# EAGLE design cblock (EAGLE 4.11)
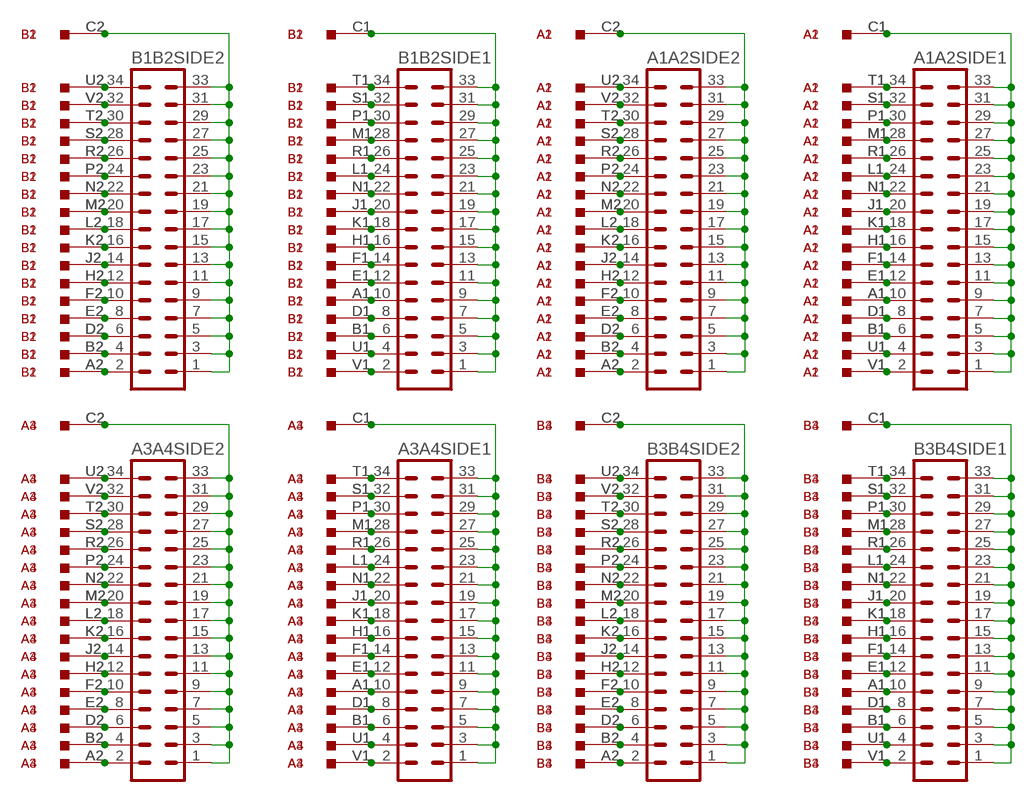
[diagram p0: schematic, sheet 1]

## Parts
A1  M916  [H807]
A1A2SIDE1  MA17-2  [MA17-2]
A1A2SIDE2  MA17-2  [MA17-2]
A2  M916  [H807]
A3  M916  [H807]
A3A4SIDE1  MA17-2  [MA17-2]
A3A4SIDE2  MA17-2  [MA17-2]
A4  M916  [H807]
B1  M916  [H807]
B1B2SIDE1  MA17-2  [MA17-2]
B1B2SIDE2  MA17-2  [MA17-2]
B2  M916  [H807]
B3  M916  [H807]
B3B4SIDE1  MA17-2  [MA17-2]
B3B4SIDE2  MA17-2  [MA17-2]
B4  M916  [H807]

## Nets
N$1: B1.C2 B1B2SIDE2.1 B1B2SIDE2.3 B1B2SIDE2.5 B1B2SIDE2.7 B1B2SIDE2.9 B1B2SIDE2.11 B1B2SIDE2.13 B1B2SIDE2.15 B1B2SIDE2.17 B1B2SIDE2.19 B1B2SIDE2.21 B1B2SIDE2.23 B1B2SIDE2.25 B1B2SIDE2.27 B1B2SIDE2.29 B1B2SIDE2.31 B1B2SIDE2.33 B2.C2
N$2: B1.A2 B1B2SIDE2.2 B2.A2
N$3: B1.B2 B1B2SIDE2.4 B2.B2
N$4: B1.D2 B1B2SIDE2.6 B2.D2
N$5: B1.E2 B1B2SIDE2.8 B2.E2
N$6: B1.F2 B1B2SIDE2.10 B2.F2
N$7: B1.H2 B1B2SIDE2.12 B2.H2
N$8: B1.J2 B1B2SIDE2.14 B2.J2
N$9: B1.K2 B1B2SIDE2.16 B2.K2
N$10: B1.L2 B1B2SIDE2.18 B2.L2
N$11: B1.M2 B1B2SIDE2.20 B2.M2
N$12: B1.N2 B1B2SIDE2.22 B2.N2
N$13: B1.P2 B1B2SIDE2.24 B2.P2
N$14: B1.R2 B1B2SIDE2.26 B2.R2
N$15: B1.S2 B1B2SIDE2.28 B2.S2
N$16: B1.T2 B1B2SIDE2.30 B2.T2
N$17: B1.U2 B1B2SIDE2.34 B2.U2
N$18: B1.V2 B1B2SIDE2.32 B2.V2
N$19: B1.A1 B1B2SIDE1.10 B2.A1
N$20: B1.B1 B1B2SIDE1.6 B2.B1
N$21: B1.D1 B1B2SIDE1.8 B2.D1
N$22: B1.E1 B1B2SIDE1.12 B2.E1
N$23: B1.F1 B1B2SIDE1.14 B2.F1
N$24: B1.H1 B1B2SIDE1.16 B2.H1
N$25: B1.J1 B1B2SIDE1.20 B2.J1
N$26: B1.K1 B1B2SIDE1.18 B2.K1
N$27: B1.L1 B1B2SIDE1.24 B2.L1
N$28: B1.M1 B1B2SIDE1.28 B2.M1
N$29: B1.N1 B1B2SIDE1.22 B2.N1
N$30: B1.P1 B1B2SIDE1.30 B2.P1
N$31: B1.R1 B1B2SIDE1.26 B2.R1
N$32: B1.S1 B1B2SIDE1.32 B2.S1
N$33: B1.T1 B1B2SIDE1.34 B2.T1
N$34: B1.U1 B1B2SIDE1.4 B2.U1
N$35: B1.V1 B1B2SIDE1.2 B2.V1
N$36: B1.C1 B1B2SIDE1.1 B1B2SIDE1.3 B1B2SIDE1.5 B1B2SIDE1.7 B1B2SIDE1.9 B1B2SIDE1.11 B1B2SIDE1.13 B1B2SIDE1.15 B1B2SIDE1.17 B1B2SIDE1.19 B1B2SIDE1.21 B1B2SIDE1.23 B1B2SIDE1.25 B1B2SIDE1.27 B1B2SIDE1.29 B1B2SIDE1.31 B1B2SIDE1.33 B2.C1
N$37: A1.C2 A1A2SIDE2.1 A1A2SIDE2.3 A1A2SIDE2.5 A1A2SIDE2.7 A1A2SIDE2.9 A1A2SIDE2.11 A1A2SIDE2.13 A1A2SIDE2.15 A1A2SIDE2.17 A1A2SIDE2.19 A1A2SIDE2.21 A1A2SIDE2.23 A1A2SIDE2.25 A1A2SIDE2.27 A1A2SIDE2.29 A1A2SIDE2.31 A1A2SIDE2.33 A2.C2
N$38: A1.A2 A1A2SIDE2.2 A2.A2
N$39: A1.B2 A1A2SIDE2.4 A2.B2
N$40: A1.D2 A1A2SIDE2.6 A2.D2
N$41: A1.E2 A1A2SIDE2.8 A2.E2
N$42: A1.F2 A1A2SIDE2.10 A2.F2
N$43: A1.H2 A1A2SIDE2.12 A2.H2
N$44: A1.J2 A1A2SIDE2.14 A2.J2
N$45: A1.K2 A1A2SIDE2.16 A2.K2
N$46: A1.L2 A1A2SIDE2.18 A2.L2
N$47: A1.M2 A1A2SIDE2.20 A2.M2
N$48: A1.N2 A1A2SIDE2.22 A2.N2
N$49: A1.P2 A1A2SIDE2.24 A2.P2
N$50: A1.R2 A1A2SIDE2.26 A2.R2
N$51: A1.S2 A1A2SIDE2.28 A2.S2
N$52: A1.T2 A1A2SIDE2.30 A2.T2
N$53: A1.U2 A1A2SIDE2.34 A2.U2
N$54: A1.V2 A1A2SIDE2.32 A2.V2
N$55: A1.A1 A1A2SIDE1.10 A2.A1
N$56: A1.B1 A1A2SIDE1.6 A2.B1
N$57: A1.D1 A1A2SIDE1.8 A2.D1
N$58: A1.E1 A1A2SIDE1.12 A2.E1
N$59: A1.F1 A1A2SIDE1.14 A2.F1
N$60: A1.H1 A1A2SIDE1.16 A2.H1
N$61: A1.J1 A1A2SIDE1.20 A2.J1
N$62: A1.K1 A1A2SIDE1.18 A2.K1
N$63: A1.L1 A1A2SIDE1.24 A2.L1
N$64: A1.M1 A1A2SIDE1.28 A2.M1
N$65: A1.N1 A1A2SIDE1.22 A2.N1
N$66: A1.P1 A1A2SIDE1.30 A2.P1
N$67: A1.R1 A1A2SIDE1.26 A2.R1
N$68: A1.S1 A1A2SIDE1.32 A2.S1
N$69: A1.T1 A1A2SIDE1.34 A2.T1
N$70: A1.U1 A1A2SIDE1.4 A2.U1
N$71: A1.V1 A1A2SIDE1.2 A2.V1
N$72: A1.C1 A1A2SIDE1.1 A1A2SIDE1.3 A1A2SIDE1.5 A1A2SIDE1.7 A1A2SIDE1.9 A1A2SIDE1.11 A1A2SIDE1.13 A1A2SIDE1.15 A1A2SIDE1.17 A1A2SIDE1.19 A1A2SIDE1.21 A1A2SIDE1.23 A1A2SIDE1.25 A1A2SIDE1.27 A1A2SIDE1.29 A1A2SIDE1.31 A1A2SIDE1.33 A2.C1
N$145: A3.C2 A3A4SIDE2.1 A3A4SIDE2.3 A3A4SIDE2.5 A3A4SIDE2.7 A3A4SIDE2.9 A3A4SIDE2.11 A3A4SIDE2.13 A3A4SIDE2.15 A3A4SIDE2.17 A3A4SIDE2.19 A3A4SIDE2.21 A3A4SIDE2.23 A3A4SIDE2.25 A3A4SIDE2.27 A3A4SIDE2.29 A3A4SIDE2.31 A3A4SIDE2.33 A4.C2
N$146: A3.A2 A3A4SIDE2.2 A4.A2
N$147: A3.B2 A3A4SIDE2.4 A4.B2
N$148: A3.D2 A3A4SIDE2.6 A4.D2
N$149: A3.E2 A3A4SIDE2.8 A4.E2
N$150: A3.F2 A3A4SIDE2.10 A4.F2
N$151: A3.H2 A3A4SIDE2.12 A4.H2
N$152: A3.J2 A3A4SIDE2.14 A4.J2
N$153: A3.K2 A3A4SIDE2.16 A4.K2
N$154: A3.L2 A3A4SIDE2.18 A4.L2
N$155: A3.M2 A3A4SIDE2.20 A4.M2
N$156: A3.N2 A3A4SIDE2.22 A4.N2
N$157: A3.P2 A3A4SIDE2.24 A4.P2
N$158: A3.R2 A3A4SIDE2.26 A4.R2
N$159: A3.S2 A3A4SIDE2.28 A4.S2
N$160: A3.T2 A3A4SIDE2.30 A4.T2
N$161: A3.U2 A3A4SIDE2.34 A4.U2
N$162: A3.V2 A3A4SIDE2.32 A4.V2
N$163: A3.A1 A3A4SIDE1.10 A4.A1
N$164: A3.B1 A3A4SIDE1.6 A4.B1
N$165: A3.D1 A3A4SIDE1.8 A4.D1
N$166: A3.E1 A3A4SIDE1.12 A4.E1
N$167: A3.F1 A3A4SIDE1.14 A4.F1
N$168: A3.H1 A3A4SIDE1.16 A4.H1
N$169: A3.J1 A3A4SIDE1.20 A4.J1
N$170: A3.K1 A3A4SIDE1.18 A4.K1
N$171: A3.L1 A3A4SIDE1.24 A4.L1
N$172: A3.M1 A3A4SIDE1.28 A4.M1
N$173: A3.N1 A3A4SIDE1.22 A4.N1
N$174: A3.P1 A3A4SIDE1.30 A4.P1
N$175: A3.R1 A3A4SIDE1.26 A4.R1
N$176: A3.S1 A3A4SIDE1.32 A4.S1
N$177: A3.T1 A3A4SIDE1.34 A4.T1
N$178: A3.U1 A3A4SIDE1.4 A4.U1
N$179: A3.V1 A3A4SIDE1.2 A4.V1
N$180: A3.C1 A3A4SIDE1.1 A3A4SIDE1.3 A3A4SIDE1.5 A3A4SIDE1.7 A3A4SIDE1.9 A3A4SIDE1.11 A3A4SIDE1.13 A3A4SIDE1.15 A3A4SIDE1.17 A3A4SIDE1.19 A3A4SIDE1.21 A3A4SIDE1.23 A3A4SIDE1.25 A3A4SIDE1.27 A3A4SIDE1.29 A3A4SIDE1.31 A3A4SIDE1.33 A4.C1
N$253: B3.C2 B3B4SIDE2.1 B3B4SIDE2.3 B3B4SIDE2.5 B3B4SIDE2.7 B3B4SIDE2.9 B3B4SIDE2.11 B3B4SIDE2.13 B3B4SIDE2.15 B3B4SIDE2.17 B3B4SIDE2.19 B3B4SIDE2.21 B3B4SIDE2.23 B3B4SIDE2.25 B3B4SIDE2.27 B3B4SIDE2.29 B3B4SIDE2.31 B3B4SIDE2.33 B4.C2
N$254: B3.A2 B3B4SIDE2.2 B4.A2
N$255: B3.B2 B3B4SIDE2.4 B4.B2
N$256: B3.D2 B3B4SIDE2.6 B4.D2
N$257: B3.E2 B3B4SIDE2.8 B4.E2
N$258: B3.F2 B3B4SIDE2.10 B4.F2
N$259: B3.H2 B3B4SIDE2.12 B4.H2
N$260: B3.J2 B3B4SIDE2.14 B4.J2
N$261: B3.K2 B3B4SIDE2.16 B4.K2
N$262: B3.L2 B3B4SIDE2.18 B4.L2
N$263: B3.M2 B3B4SIDE2.20 B4.M2
N$264: B3.N2 B3B4SIDE2.22 B4.N2
N$265: B3.P2 B3B4SIDE2.24 B4.P2
N$266: B3.R2 B3B4SIDE2.26 B4.R2
N$267: B3.S2 B3B4SIDE2.28 B4.S2
N$268: B3.T2 B3B4SIDE2.30 B4.T2
N$269: B3.U2 B3B4SIDE2.34 B4.U2
N$270: B3.V2 B3B4SIDE2.32 B4.V2
N$271: B3.A1 B3B4SIDE1.10 B4.A1
N$272: B3.B1 B3B4SIDE1.6 B4.B1
N$273: B3.D1 B3B4SIDE1.8 B4.D1
N$274: B3.E1 B3B4SIDE1.12 B4.E1
N$275: B3.F1 B3B4SIDE1.14 B4.F1
N$276: B3.H1 B3B4SIDE1.16 B4.H1
N$277: B3.J1 B3B4SIDE1.20 B4.J1
N$278: B3.K1 B3B4SIDE1.18 B4.K1
N$279: B3.L1 B3B4SIDE1.24 B4.L1
N$280: B3.M1 B3B4SIDE1.28 B4.M1
N$281: B3.N1 B3B4SIDE1.22 B4.N1
N$282: B3.P1 B3B4SIDE1.30 B4.P1
N$283: B3.R1 B3B4SIDE1.26 B4.R1
N$284: B3.S1 B3B4SIDE1.32 B4.S1
N$285: B3.T1 B3B4SIDE1.34 B4.T1
N$286: B3.U1 B3B4SIDE1.4 B4.U1
N$287: B3.V1 B3B4SIDE1.2 B4.V1
N$288: B3.C1 B3B4SIDE1.1 B3B4SIDE1.3 B3B4SIDE1.5 B3B4SIDE1.7 B3B4SIDE1.9 B3B4SIDE1.11 B3B4SIDE1.13 B3B4SIDE1.15 B3B4SIDE1.17 B3B4SIDE1.19 B3B4SIDE1.21 B3B4SIDE1.23 B3B4SIDE1.25 B3B4SIDE1.27 B3B4SIDE1.29 B3B4SIDE1.31 B3B4SIDE1.33 B4.C1

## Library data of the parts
A1-A4 B1-B4 = dec-m:M916: Simple 36 pin connector/wire cable
A1A2SIDE1 A1A2SIDE2 A3A4SIDE1 A3A4SIDE2 B1B2SIDE1 B1B2SIDE2 B3B4SIDE1 B3B4SIDE2 = con-lstb:MA17-2: PIN HEADER

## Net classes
1 Power: width 0.305 mm, drill 0.305 mm

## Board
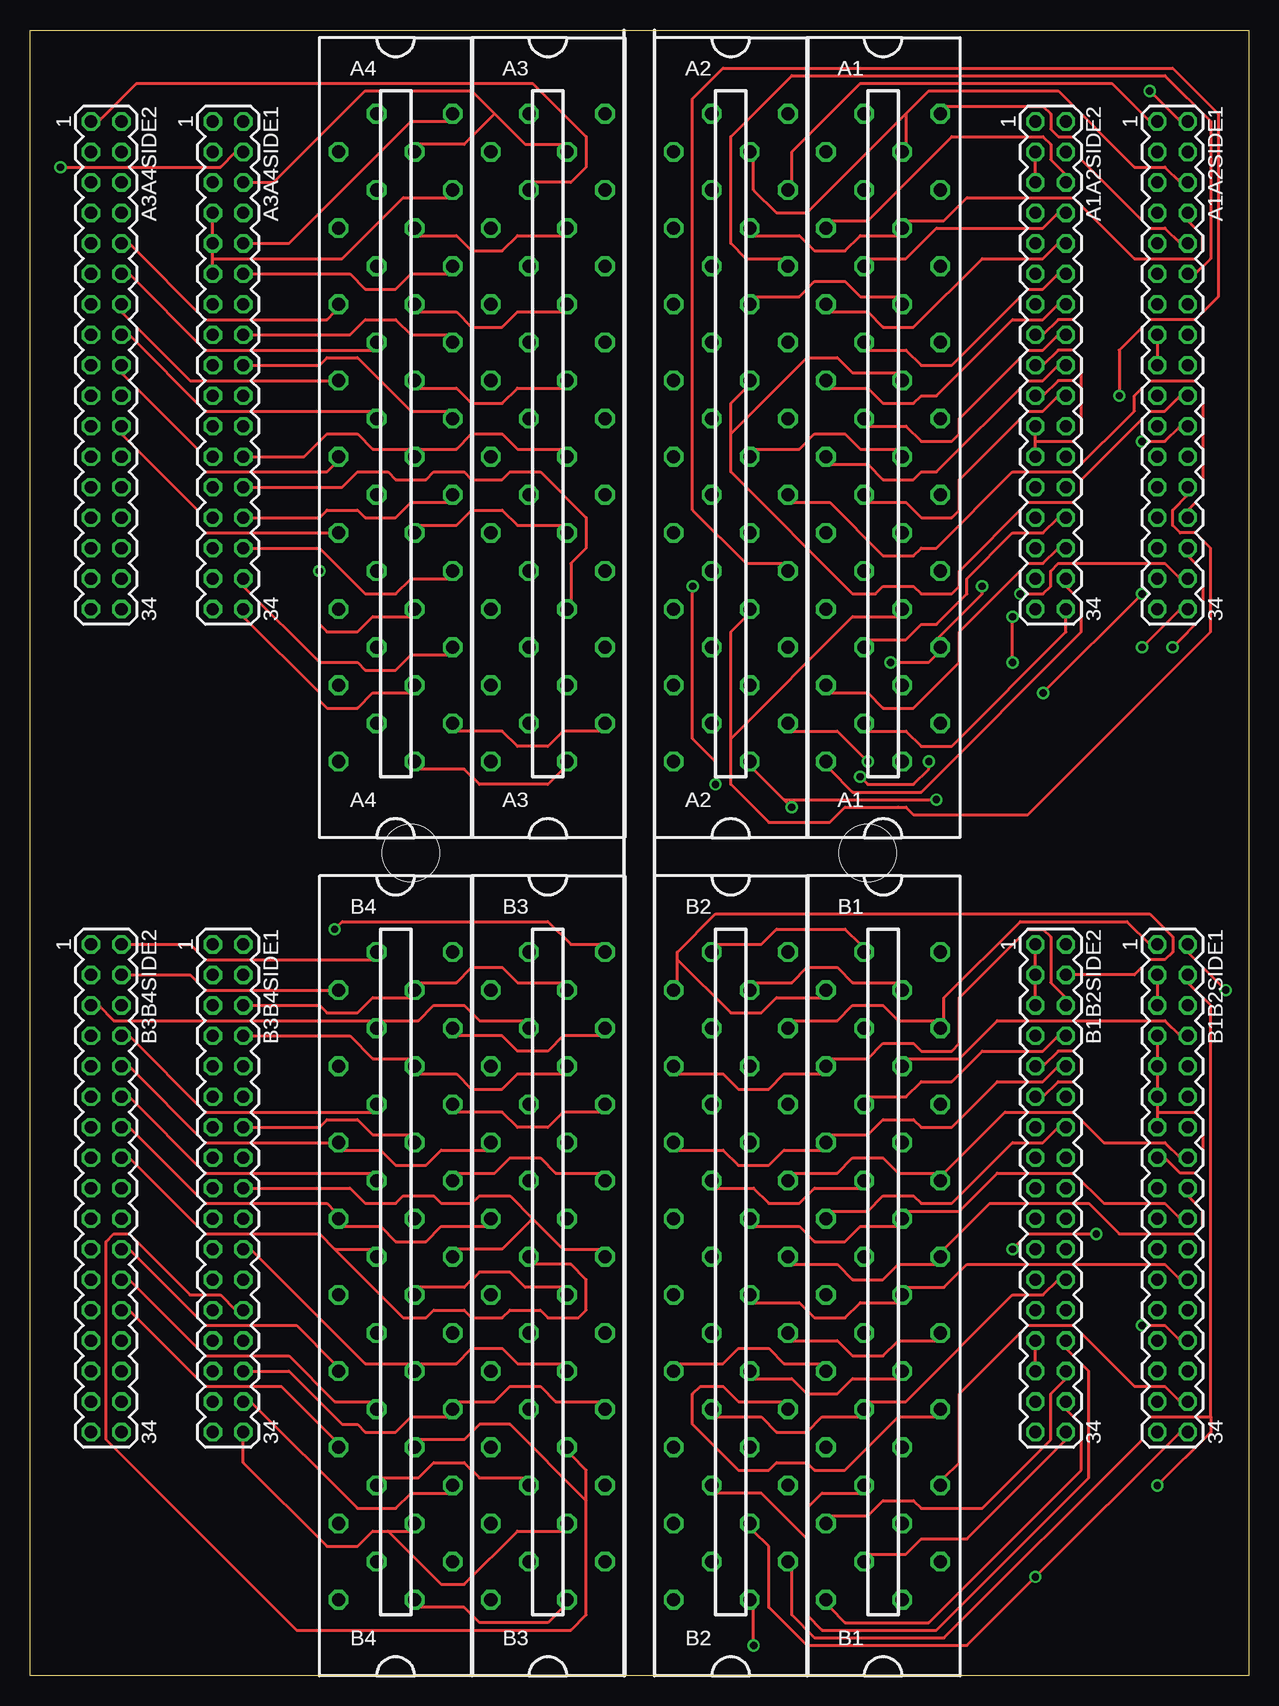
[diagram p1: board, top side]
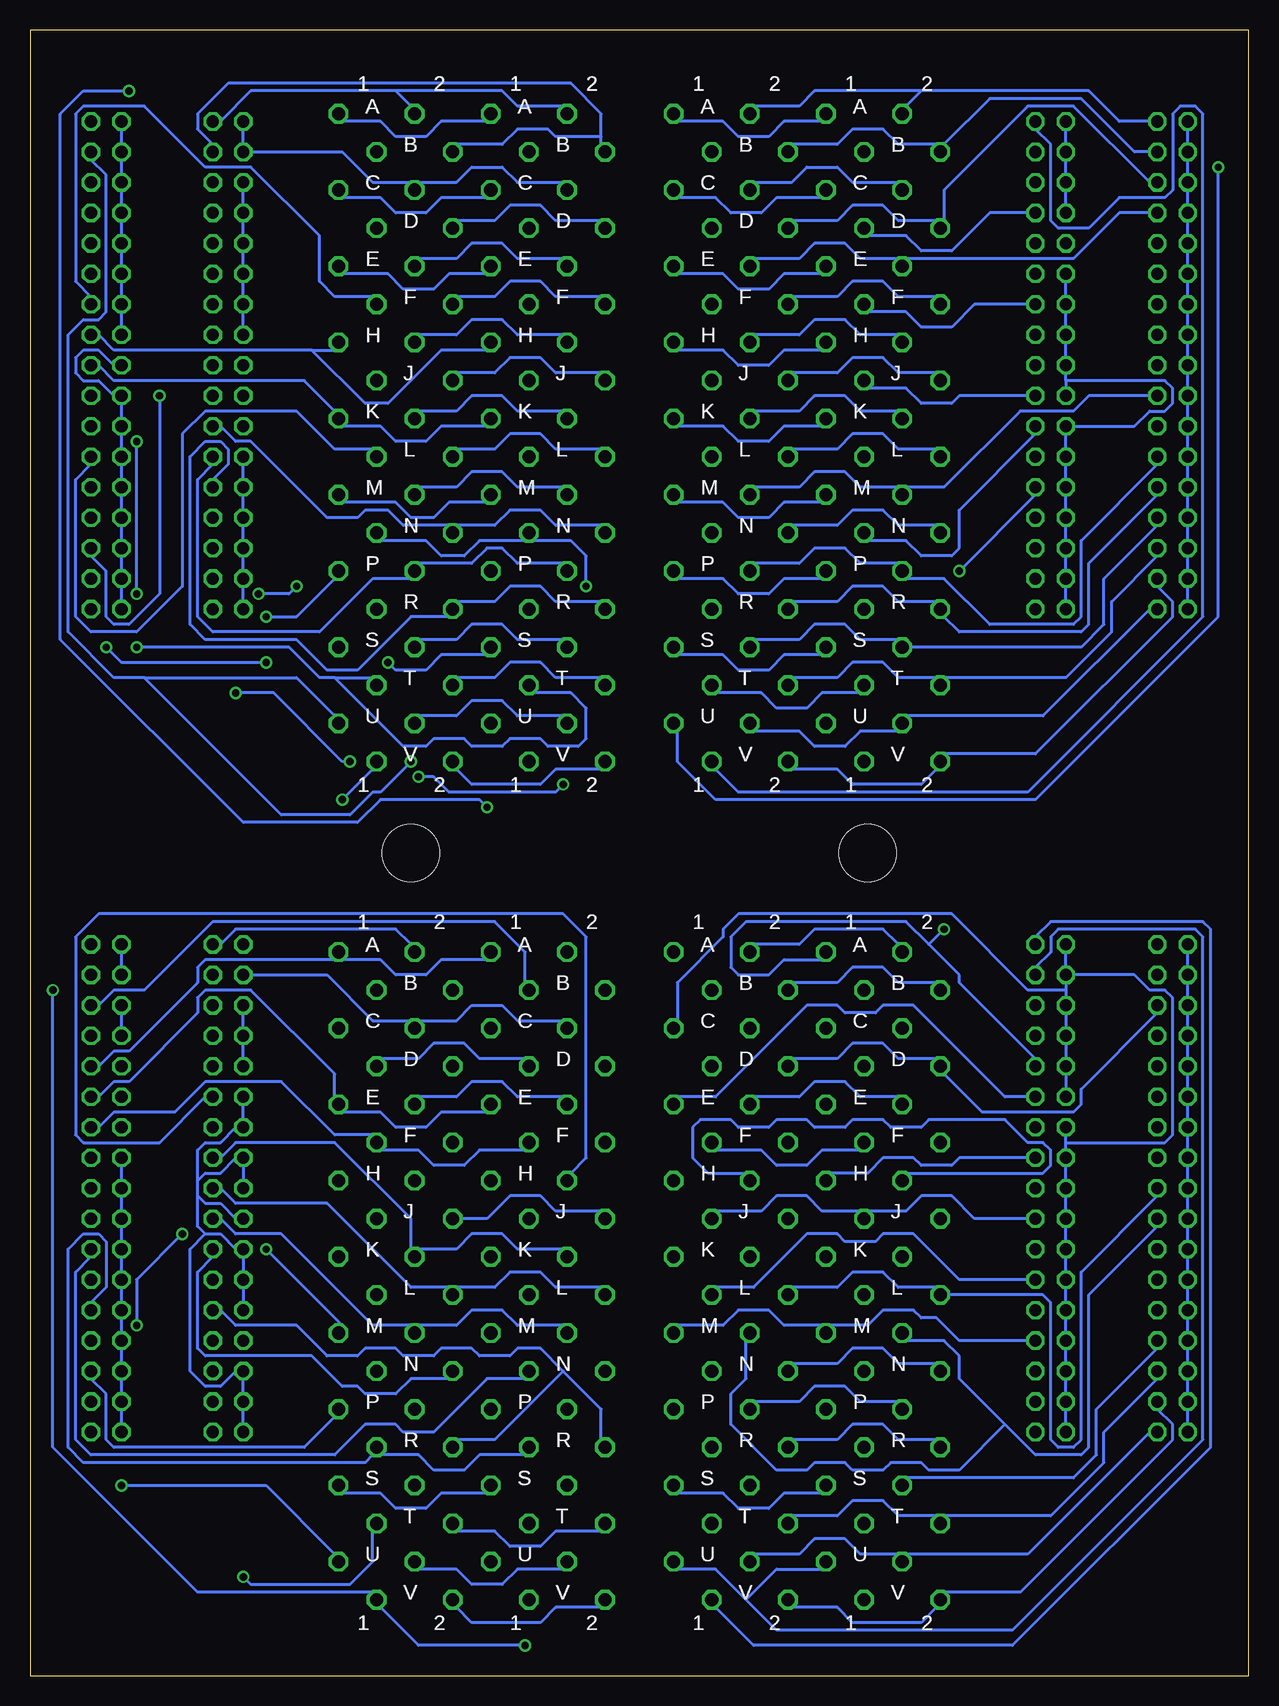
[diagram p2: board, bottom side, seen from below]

Size 101.6 x 137.16 mm. Coordinates in mm from the lower left corner, seen from the top.
Outline: 101.6,0 52.07,0 49.53,0 0,0 0,137.16 49.53,137.16 52.07,137.16 101.6,137.16 101.6,0
Copper layers (1*16): Top 0.035mm / dielectric 1.5mm / Bottom 0.035mm
Design rules "custompcb": minimum track width 10mil, minimum drill 24mil, track to track 12mil, track to pad 12mil, pad to pad 12mil, via to via 12mil, smd to smd 12mil, copper to edge 40mil, drill to drill 12mil, minimum pad ring 10mil, minimum via ring 8mil, stop-mask expansion 0mil, vias tented up to drill 0mil, thermal gap 10mil
Holes 4.78 mm at 31.75,68.58 69.85,68.58

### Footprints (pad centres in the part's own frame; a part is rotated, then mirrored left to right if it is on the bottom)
H807 = drill 1.092 octagon: A1 4.763,28.575; A2 -1.587,28.575; B1 1.587,25.4; B2 -4.763,25.4; C1 4.763,22.225; C2 -1.587,22.225; D1 1.587,19.05; D2 -4.763,19.05; E1 4.763,15.875; E2 -1.587,15.875; F1 1.587,12.7; F2 -4.763,12.7; H1 4.763,9.525; H2 -1.587,9.525; J1 1.587,6.35; J2 -4.763,6.35; K1 4.763,3.175; K2 -1.587,3.175; L1 1.587,0; L2 -4.763,0; M1 4.763,-3.175; M2 -1.587,-3.175; N1 1.587,-6.35; N2 -4.763,-6.35; P1 4.763,-9.525; P2 -1.587,-9.525; R1 1.587,-12.7; R2 -4.763,-12.7; S1 4.763,-15.875; S2 -1.587,-15.875; T1 1.587,-19.05; T2 -4.763,-19.05; U1 4.763,-22.225; U2 -1.587,-22.225; V1 1.587,-25.4; V2 -4.763,-25.4
MA17-2 = drill 1.016 octagon: 1 -20.32,-1.27; 2 -20.32,1.27; 3 -17.78,-1.27; 4 -17.78,1.27; 5 -15.24,-1.27; 6 -15.24,1.27; 7 -12.7,-1.27; 8 -12.7,1.27; 9 -10.16,-1.27; 10 -10.16,1.27; 11 -7.62,-1.27; 12 -7.62,1.27; 13 -5.08,-1.27; 14 -5.08,1.27; 15 -2.54,-1.27; 16 -2.54,1.27; 17 0,-1.27; 18 0,1.27; 19 2.54,-1.27; 20 2.54,1.27; 21 5.08,-1.27; 22 5.08,1.27; 23 7.62,-1.27; 24 7.62,1.27; 25 10.16,-1.27; 26 10.16,1.27; 27 12.7,-1.27; 28 12.7,1.27; 29 15.24,-1.27; 30 15.24,1.27; 31 17.78,-1.27; 32 17.78,1.27; 33 20.32,-1.27; 34 20.32,1.27

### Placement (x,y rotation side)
A1  71.12,101.6 0 top
A1A2SIDE1  95.25,109.22 270 top
A1A2SIDE2  85.09,109.22 270 top
A2  58.42,101.6 0 top
A3  43.18,101.6 0 top
A3A4SIDE1  16.51,109.22 270 top
A3A4SIDE2  6.35,109.22 270 top
A4  30.48,101.6 0 top
B1  71.12,31.75 0 top
B1B2SIDE1  95.25,40.64 270 top
B1B2SIDE2  85.09,40.64 270 top
B2  58.42,31.75 0 top
B3  43.18,31.75 0 top
B3B4SIDE1  16.51,40.64 270 top
B3B4SIDE2  6.35,40.64 270 top
B4  30.48,31.75 0 top

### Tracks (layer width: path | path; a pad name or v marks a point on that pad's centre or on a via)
N$1
  Top 0.254: B1B2SIDE2.27 83.82,27.3 83.82,26.04 B1B2SIDE2.29 | B1B2SIDE2.1 83.82,60.33 83.82,59.05 B1B2SIDE2.3 83.82,57.78 83.82,56.52 B1B2SIDE2.5 | B1B2SIDE2.11 84.45,48.26 85.72,49.53 87,49.53 87.63,50.16 87.63,51.44 87,52.07 85.72,52.07 84.45,50.8 B1B2SIDE2.9
  Bottom 0.254: B1B2SIDE2.33 83.82,20.95 83.82,22.23 B1B2SIDE2.31 83.82,23.5 83.82,24.77 B1B2SIDE2.29 84.45,25.4 85.72,24.13 87,24.13 88.27,25.4 88.27,35.56 87,36.83 | B1B2SIDE2.25 83.82,31.11 83.82,32.38 B1B2SIDE2.23 83.82,33.66 83.82,34.92 B1B2SIDE2.21 84.45,35.56 85.72,36.83 87,36.83 | B1B2SIDE2.11 83.82,47.62 83.82,46.35 B1B2SIDE2.13 84.45,45.72 85.72,44.45 87,44.45 87.63,43.81 87.63,41.27 | 87.63,40.01 87,39.37 85.72,39.37 84.45,38.1 B1B2SIDE2.19 | 87.63,40.01 87.63,41.27 | 87.63,41.27 87,41.91 85.72,41.91 84.45,43.18 B1B2SIDE2.15 83.82,42.55 83.82,41.27 B1B2SIDE2.17 | 87,36.83 87.63,37.47 87.63,40.01 | B1B2SIDE2.9 83.82,51.44 83.82,52.7 B1B2SIDE2.7 83.82,53.98 83.82,55.24 B1B2SIDE2.5 | B1B2SIDE2.3 83.19,58.42 76.83,58.42 73.03,54.61 69.85,54.61 B1.C2 69.22,54.61 66.04,54.61 64.77,55.88 62.23,55.88 60.96,54.61 57.15,54.61 B2.C2
N$2
  Top 0.254: B2.A2 57.15,60.96 60.96,60.96 62.23,62.23 67.94,62.23 69.22,60.96 B1.A2
  Bottom 0.254: B1B2SIDE2.2 85.72,60.96 84.45,62.23 71.12,62.23 69.85,60.96 B1.A2
N$3
  Top 0.254: 53.98,59.69 53.98,57.78 B2.B2 | 53.98,59.69 53.98,60.33 57.15,63.5 93.34,63.5 95.25,61.59 95.25,60.33 94.61,59.69 93.34,59.69 92.08,58.42 87,58.42 B1B2SIDE2.4 | 53.98,59.69 58.42,55.24 60.96,55.24 62.23,56.52 66.04,56.52 B1.B2
N$4
  Top 0.254: B1B2SIDE2.6 86.36,56.52 85.09,57.78 85.09,61.59 84.45,62.23 83.19,62.23 77.47,56.52 77.47,52.7 76.83,52.07 74.3,52.07 73.66,52.7 71.12,52.7 69.85,51.44 66.67,51.44 B1.D2 66.04,50.16 62.87,50.16 61.59,48.9 59.05,48.9 57.78,50.16 53.98,50.16 B2.D2
N$5
  Top 0.254: B1B2SIDE2.8 85.72,53.34 84.45,52.07 79.38,52.07 76.83,49.53 74.3,49.53 73.03,48.26 69.85,48.26 B1.E2
  Bottom 0.254: B2.E2 57.15,48.26 60.96,48.26 62.23,49.53 64.77,49.53 66.04,48.26 69.22,48.26 B1.E2
N$6
  Top 0.254: B1B2SIDE2.10 85.72,50.8 84.45,49.53 80.64,49.53 76.83,45.72 74.3,45.72 73.66,46.35 71.12,46.35 69.85,45.09 66.67,45.09 B1.F2 66.04,43.81 62.87,43.81 61.59,42.55 59.05,42.55 57.78,43.81 53.98,43.81 B2.F2
N$7
  Top 0.254: B1.H2 69.22,40.64 65.41,40.64 64.14,39.37 61.59,39.37 60.33,40.64 57.15,40.64 B2.H2
  Bottom 0.254: B1B2SIDE2.12 87,48.26 90.81,44.45 97.16,44.45 97.79,45.09 97.79,61.59 95.89,63.5 57.15,63.5 55.24,61.59 55.24,43.18 56.52,41.91 B2.H2
N$8
  Top 0.254: B1B2SIDE2.14 85.72,45.72 84.45,44.45 81.92,44.45 76.83,39.37 74.3,39.37 73.66,40.01 71.12,40.01 69.85,38.73 66.67,38.73 B1.J2
  Bottom 0.254: B2.J2 53.98,38.73 57.78,38.73 59.05,40.01 61.59,40.01 63.5,38.1 66.04,38.1 B1.J2
N$9
  Bottom 0.254: B1B2SIDE2.16 85.72,43.18 84.45,44.45 76.2,44.45 69.85,38.1 69.85,35.56 B1.K2 69.22,35.56 66.04,35.56 64.77,36.83 62.23,36.83 60.96,35.56 57.15,35.56 B2.K2
N$10
  Bottom 0.254: B1B2SIDE2.18 85.72,40.64 84.45,39.37 76.83,39.37 69.85,32.38 66.67,32.38 B1.L2 66.04,32.38 62.87,32.38 61.59,33.66 59.05,33.66 57.78,32.38 53.98,32.38 B2.L2
N$11
  Bottom 0.254: B1B2SIDE2.20 85.72,38.1 84.45,36.83 80.64,36.83 73.03,29.21 69.85,29.21 B1.M2 69.22,29.21 66.04,29.21 64.77,30.48 62.23,30.48 60.96,29.21 57.15,29.21 B2.M2
N$12
  Top 0.254: B2.N2 53.98,26.04 57.78,26.04 59.05,27.3 61.59,27.3 62.87,26.04 66.04,26.04 B1.N2
  Bottom 0.254: B1B2SIDE2.22 86.36,34.92 87.63,33.66 87.63,27.3 87,26.67 78.11,26.67 75.56,24.13 74.3,24.13 73.66,23.5 71.12,23.5 69.85,24.77 66.67,24.77 B1.N2
N$13
  Top 0.254: B1B2SIDE2.24 85.72,33.02 84.45,31.75 81.92,31.75 73.03,22.86 69.85,22.86 B1.P2 69.22,21.59 66.04,21.59 64.77,20.32 62.23,20.32 60.96,21.59 57.15,21.59 B2.P2
N$14
  Bottom 0.254: 57.15,25.4 53.98,22.23 53.98,19.68 B2.R2 | 57.15,25.4 59.05,27.3 60.96,27.3 61.59,26.67 64.14,26.67 64.77,27.3 67.31,27.3 67.94,26.67 70.48,26.67 71.12,27.3 73.66,27.3 74.3,26.67 76.83,26.67 79.38,29.21 84.45,29.21 85.72,30.48 B1B2SIDE2.26 | 57.15,25.4 62.87,19.68 66.04,19.68 B1.R2
N$15
  Top 0.254: 64.77,11.43 64.77,13.97 66.04,15.24 69.22,15.24 B1.S2 | 64.77,11.43 64.77,5.08 66.04,3.81 75.56,3.81 88.27,16.51 88.27,25.4 86.36,27.3 B1B2SIDE2.28 | 64.77,11.43 60.96,15.24 57.15,15.24 B2.S2
N$16
  Top 0.254: B1B2SIDE2.30 86.36,24.77 85.09,23.5 85.09,19.68 79.38,13.97 74.3,13.97 73.66,14.61 71.12,14.61 69.85,13.34 66.67,13.34 B1.T2
  Bottom 0.254: B2.T2 53.98,12.06 57.78,12.06 59.05,10.79 61.59,10.79 62.87,12.06 66.04,12.06 B1.T2
N$17
  Top 0.254: B1B2SIDE2.34 86.36,19.68 78.11,11.43 74.3,11.43 73.03,10.16 69.85,10.16 B1.U2
  Bottom 0.254: B2.U2 57.15,8.89 60.96,8.89 62.23,7.62 64.77,7.62 66.04,8.89 69.22,8.89 B1.U2
N$18
  Top 0.254: B1B2SIDE2.32 86.36,22.23 87.63,20.95 87.63,17.14 74.93,4.45 67.94,4.45 66.67,5.71 B1.V2
  Bottom 0.254: B2.V2 53.98,5.71 57.78,5.71 59.05,4.45 64.77,4.45 66.04,5.71 B1.V2
N$19
  Bottom 0.254: B1B2SIDE1.10 95.89,50.8 94.61,52.07 93.34,52.07 87.63,57.78 87.63,59.05 87,59.69 76.2,59.69 B1.A1 75.56,59.69 72.39,59.69 71.12,58.42 68.58,58.42 67.31,59.69 63.5,59.69 B2.A1
N$20
  Top 0.254: B1.B1 72.39,57.78 68.58,57.78 67.31,59.05 64.77,59.05 63.5,57.78 60.33,57.78 B2.B1
  Bottom 0.254: B1B2SIDE1.6 95.89,55.88 94.61,57.15 92.08,57.15 86.36,62.87 62.87,62.87 60.33,60.33 60.33,57.78 B2.B1
N$21
  Top 0.254: B1B2SIDE1.8 95.89,53.34 94.61,54.61 80.64,54.61 77.47,51.44 73.03,51.44 B1.D1
  Bottom 0.254: B2.D1 60.33,51.44 64.14,51.44 65.41,52.7 67.94,52.7 69.22,51.44 72.39,51.44 B1.D1
N$22
  Bottom 0.254: B1B2SIDE1.12 95.89,48.26 94.61,49.53 93.34,49.53 87.63,55.24 87.63,56.52 87,57.15 83.19,57.15 76.2,50.16 76.2,48.26 B1.E1 75.56,46.99 72.39,46.99 71.12,45.72 68.58,45.72 67.31,46.99 63.5,46.99 B2.E1
N$23
  Bottom 0.254: B1B2SIDE1.14 95.89,45.72 94.61,46.99 89.53,46.99 87,49.53 80.64,49.53 76.2,45.09 73.03,45.09 B1.F1 72.39,43.81 69.22,43.81 67.94,42.55 65.41,42.55 64.14,43.81 60.33,43.81 B2.F1
N$24
  Top 0.254: B1B2SIDE1.16 95.89,43.18 94.61,44.45 89.53,44.45 87,46.99 81.28,46.99 76.2,41.91 B1.H1 75.56,41.91 72.39,41.91 71.12,43.18 68.58,43.18 67.31,41.91 63.5,41.91 B2.H1
N$25
  Top 0.254: B1B2SIDE1.20 95.89,38.1 94.61,39.37 89.53,39.37 87,41.91 80.64,41.91 77.47,38.73 73.03,38.73 B1.J1 72.39,37.47 69.22,37.47 67.94,36.2 65.41,36.2 64.14,37.47 60.33,37.47 B2.J1
N$26
  Top 0.254: B1B2SIDE1.18 96.52,40.01 97.79,38.73 97.79,37.47 97.16,36.83 90.81,36.83 88.27,39.37 80.01,39.37 76.2,35.56 B1.K1 75.56,34.29 72.39,34.29 71.12,33.02 68.58,33.02 67.31,34.29 63.5,34.29 B2.K1
N$27
  Top 0.254: B1B2SIDE1.24 95.89,33.02 94.61,34.29 78.11,34.29 76.2,32.38 73.03,32.38 B1.L1 72.39,31.11 69.22,31.11 67.94,29.84 65.41,29.84 64.14,31.11 60.33,31.11 B2.L1
N$28  (via drill 0.61)
  Top 0.254: v92.71,29.21 94.61,29.21 95.89,27.94 B1B2SIDE1.28 | v88.9,36.83 83.19,36.83 v81.92,35.56 | B2.M1 63.5,27.94 67.31,27.94 68.58,26.67 71.12,26.67 72.39,27.94 75.56,27.94 B1.M1
  Bottom 0.254: v92.71,29.21 92.71,33.02 v88.9,36.83 | v81.92,35.56 75.56,29.21 B1.M1
N$29
  Top 0.254: B1.N1 72.39,24.77 68.58,24.77 67.31,23.5 64.77,23.5 63.5,24.77 60.33,24.77 B2.N1
  Bottom 0.254: B1B2SIDE1.22 96.52,34.92 97.79,33.66 97.79,19.68 96.52,18.41 76.2,18.41 73.66,20.95 71.12,20.95 70.48,20.32 67.94,20.32 63.5,24.77 60.33,24.77 B2.N1
N$30
  Top 0.254: B2.P1 62.87,22.86 59.05,22.86 57.78,24.13 55.88,24.13 55.24,23.5 55.24,20.95 59.05,17.14 61.59,17.14 62.23,17.78 64.77,17.78 65.41,17.14 67.94,17.14 72.39,21.59 75.56,21.59 B1.P1
  Bottom 0.254: B1B2SIDE1.30 96.52,24.77 95.25,23.5 95.25,19.68 94.61,19.05 78.74,19.05 76.2,21.59 B1.P1
N$31
  Bottom 0.254: B1B2SIDE1.26 96.52,31.11 95.25,32.38 95.25,36.2 95.89,36.83 97.16,36.83 98.42,35.56 98.42,19.05 97.16,17.78 73.66,17.78 73.03,18.41 B1.R1 72.39,18.41 69.22,18.41 67.94,17.14 65.41,17.14 64.14,18.41 60.33,18.41 B2.R1
N$32
  Top 0.254: B1B2SIDE1.32 95.89,22.86 94.61,24.13 92.08,24.13 87,29.21 83.19,29.21 77.47,23.5 77.47,17.78 76.2,16.51 B1.S1
  Bottom 0.254: B2.S1 63.5,15.24 67.31,15.24 68.58,13.97 71.12,13.97 72.39,15.24 75.56,15.24 B1.S1
N$33  (via drill 0.61)
  Top 0.254: B1B2SIDE1.34 95.89,20.32 v83.82,8.26 78.11,2.54 64.77,2.54 61.59,5.71 61.59,10.79 60.33,12.06 B2.T1
  Bottom 0.254: v83.82,8.26 83.19,7.62 74.93,7.62 73.03,9.53 73.03,12.06 B1.T1
N$34  (via drill 0.61)
  Top 0.254: 98.42,21.59 98.42,20.32 v93.98,15.88 | 98.42,21.59 98.42,55.88 96.52,57.78 B1B2SIDE1.4 | 98.42,21.59 93.34,21.59 92.71,20.95 92.71,19.68 76.2,3.17 65.41,3.17 63.5,5.08 63.5,8.89 B2.U1
  Bottom 0.254: v93.98,15.88 81.92,15.88 76.2,10.16 B1.U1
N$35  (via drill 0.61)
  Top 0.254: v99.69,57.15 96.52,60.33 B1B2SIDE1.2 | v60.33,2.54 60.33,5.71 B2.V1
  Bottom 0.254: v99.69,57.15 99.69,19.05 87.63,6.99 73.03,6.99 B1.V1 72.39,5.71 69.22,2.54 v60.33,2.54
N$36
  Top 0.254: B2.C1 63.5,54.61 67.31,54.61 68.58,55.88 71.12,55.88 72.39,54.61 75.56,54.61 B1.C1 76.2,54.61 76.2,56.52 82.55,62.87 91.44,62.87 93.34,60.96 B1B2SIDE1.1 | 93.98,46.99 93.98,47.62 B1B2SIDE1.11 93.98,48.9 93.98,50.16 B1B2SIDE1.9 93.98,51.44 93.98,52.7 B1B2SIDE1.7 | 93.98,46.99 93.98,46.35 B1B2SIDE1.13 | B1B2SIDE1.3 93.98,57.78 93.98,56.52 B1B2SIDE1.5 | 93.98,46.99 97.16,46.99 97.79,46.35 97.79,42.55 97.16,41.91 95.89,41.91 94.61,43.18 B1B2SIDE1.15
  Bottom 0.254: B1B2SIDE1.33 93.98,20.95 93.98,22.23 B1B2SIDE1.31 93.98,23.5 93.98,24.77 B1B2SIDE1.29 93.98,26.04 93.98,27.3 B1B2SIDE1.27 93.98,28.57 93.98,29.84 B1B2SIDE1.25 93.98,31.11 93.98,32.38 B1B2SIDE1.23 93.98,33.66 93.98,34.92 B1B2SIDE1.21 93.98,36.2 93.98,37.47 B1B2SIDE1.19 93.98,38.73 93.98,40.01 B1B2SIDE1.17 93.98,41.27 93.98,42.55 B1B2SIDE1.15 | B1B2SIDE1.3 93.98,59.05 93.98,60.33 B1B2SIDE1.1 | B1B2SIDE1.7 93.98,53.98 93.98,55.24 B1B2SIDE1.5
N$37
  Top 0.254: 83.82,102.87 83.82,102.23 A1A2SIDE2.23 | 83.82,102.87 83.82,103.5 A1A2SIDE2.21 | 87.63,107.31 87,107.95 85.72,107.95 84.45,106.68 A1A2SIDE2.19 | 87.63,107.31 87.63,103.5 87,102.87 83.82,102.87 | 87,110.49 85.72,110.49 84.45,109.22 A1A2SIDE2.17 | 87,110.49 87.63,109.86 87.63,107.31 | A1A2SIDE2.5 83.82,125.09 83.82,126.36 A1A2SIDE2.3 | 87,110.49 87.63,111.12 87.63,112.39 87,113.03 85.72,113.03 84.45,111.76 A1A2SIDE2.15
  Bottom 0.254: A1A2SIDE2.33 83.82,89.53 83.82,90.81 A1A2SIDE2.31 83.82,92.08 83.82,93.34 A1A2SIDE2.29 83.82,94.61 83.82,95.89 A1A2SIDE2.27 83.82,97.16 83.82,98.42 A1A2SIDE2.25 83.82,99.69 83.82,100.97 A1A2SIDE2.23 | A1A2SIDE2.15 83.82,112.39 83.82,113.67 A1A2SIDE2.13 83.82,114.94 83.82,116.2 A1A2SIDE2.11 83.82,117.47 83.82,118.75 A1A2SIDE2.9 83.82,120.02 83.82,121.28 A1A2SIDE2.7 83.82,122.56 83.82,123.83 A1A2SIDE2.5 | A1A2SIDE2.1 83.82,128.91 83.82,127.64 A1A2SIDE2.3 83.19,127 75.56,127 73.03,124.46 69.85,124.46 A1.C2 69.22,124.46 66.04,124.46 64.77,125.73 62.23,125.73 60.96,124.46 57.15,124.46 A2.C2
N$38
  Bottom 0.254: 71.12,132.08 83.19,132.08 85.72,129.54 A1A2SIDE2.2 | 71.12,132.08 69.85,130.81 A1.A2 | 71.12,132.08 62.23,132.08 60.96,130.81 57.15,130.81 A2.A2
N$39
  Bottom 0.254: 53.98,128.27 53.98,127.64 A2.B2 | 53.98,128.27 53.98,130.18 56.52,132.72 85.09,132.72 87.63,130.18 87.63,128.91 86.36,127.64 A1A2SIDE2.4 | 53.98,128.27 57.78,128.27 58.42,128.91 60.96,128.91 62.23,127.64 66.04,127.64 A1.B2
N$40
  Top 0.254: A1A2SIDE2.6 86.36,125.09 85.09,126.36 85.09,127.64 84.45,128.27 76.83,128.27 69.85,121.28 66.67,121.28 A1.D2
  Bottom 0.254: A2.D2 53.98,121.28 57.78,121.28 59.05,122.56 61.59,122.56 62.87,121.28 66.04,121.28 A1.D2
N$41
  Top 0.254: A1A2SIDE2.8 85.72,121.92 84.45,120.65 75.56,120.65 73.03,118.11 69.85,118.11 A1.E2
  Bottom 0.254: A2.E2 57.15,118.11 60.96,118.11 62.23,119.38 64.77,119.38 66.04,118.11 69.22,118.11 A1.E2
N$42
  Top 0.254: A1A2SIDE2.10 85.72,119.38 84.45,118.11 79.38,118.11 73.66,112.39 71.12,112.39 69.85,113.67 66.67,113.67 A1.F2
  Bottom 0.254: A2.F2 53.98,114.94 57.78,114.94 59.05,116.2 61.59,116.2 62.87,114.94 66.04,114.94 A1.F2
N$43
  Top 0.254: A1A2SIDE2.12 85.72,116.84 84.45,115.57 83.19,115.57 76.83,109.22 74.3,109.22 73.03,110.49 69.85,110.49 A1.H2
  Bottom 0.254: A2.H2 57.15,111.76 60.96,111.76 62.23,113.03 64.77,113.03 66.04,111.76 69.22,111.76 A1.H2
N$44
  Top 0.254: A1A2SIDE2.14 85.72,114.3 84.45,113.03 81.92,113.03 75.56,106.68 74.3,106.68 73.66,106.05 71.12,106.05 69.85,107.31 66.67,107.31 A1.J2
  Bottom 0.254: A2.J2 53.98,108.58 57.78,108.58 59.05,109.86 61.59,109.86 62.87,108.58 66.04,108.58 A1.J2
N$45
  Top 0.254: A1A2SIDE2.16 85.72,111.76 84.45,110.49 83.19,110.49 77.47,104.78 77.47,103.5 76.83,102.87 74.3,102.87 73.03,104.14 69.85,104.14 A1.K2
  Bottom 0.254: A2.K2 57.15,105.41 60.96,105.41 62.23,106.68 64.77,106.68 66.04,105.41 69.22,105.41 A1.K2
N$46
  Top 0.254: A1A2SIDE2.18 85.72,109.22 84.45,107.95 83.19,107.95 75.56,100.33 74.3,100.33 73.66,99.69 71.12,99.69 69.85,100.97 66.67,100.97 A1.L2
  Bottom 0.254: A2.L2 53.98,102.23 57.78,102.23 59.05,103.5 61.59,103.5 62.87,102.23 66.04,102.23 A1.L2
N$47
  Top 0.254: A1A2SIDE2.20 85.72,106.68 84.45,105.41 83.19,105.41 77.47,99.69 77.47,97.16 76.83,96.52 74.3,96.52 73.03,97.79 69.85,97.79 A1.M2
  Bottom 0.254: A2.M2 57.15,99.06 60.96,99.06 62.23,100.33 64.77,100.33 66.04,99.06 69.22,99.06 A1.M2
N$48
  Bottom 0.254: A2.N2 53.98,95.89 57.78,95.89 59.05,97.16 61.59,97.16 62.87,95.89 66.04,95.89 A1.N2 66.67,95.89 70.48,95.89 71.75,97.16 73.66,97.16 74.3,96.52 76.83,96.52 83.19,102.87 84.45,102.87 85.72,104.14 A1A2SIDE2.22
N$49
  Bottom 0.254: A1A2SIDE2.24 86.36,100.97 87.63,99.69 87.63,88.27 86.36,87 77.47,87 73.03,91.44 69.85,91.44 A1.P2 69.22,92.71 64.77,92.71 63.5,93.98 62.23,93.98 60.96,92.71 57.15,92.71 A2.P2
N$50
  Bottom 0.254: A1A2SIDE2.26 86.36,99.69 85.09,100.97 85.09,102.23 85.72,102.87 87,102.87 88.27,101.6 88.27,87.63 87,86.36 79.38,86.36 76.83,83.82 74.3,83.82 69.85,88.27 66.67,88.27 A1.R2 66.04,89.53 62.87,89.53 61.59,90.81 59.05,90.81 57.78,89.53 53.98,89.53 A2.R2
N$51
  Top 0.254: A1A2SIDE2.28 85.72,96.52 84.45,95.25 81.92,95.25 78.11,91.44 78.11,90.17 75.56,87.63 74.3,87.63 73.03,86.36 69.85,86.36 A1.S2
  Bottom 0.254: A2.S2 57.15,86.36 60.96,86.36 62.23,87.63 64.77,87.63 66.04,86.36 69.22,86.36 A1.S2
N$52
  Top 0.254: A1A2SIDE2.30 85.72,93.98 84.45,92.71 83.19,92.71 77.47,87 77.47,84.45 73.66,80.64 71.12,80.64 69.85,81.92 66.67,81.92 A1.T2
  Bottom 0.254: A2.T2 53.98,83.19 57.78,83.19 59.05,84.45 61.59,84.45 62.87,83.19 66.04,83.19 A1.T2
N$53
  Top 0.254: A1A2SIDE2.34 86.36,88.27 86.36,87 76.83,77.47 74.3,77.47 73.03,78.74 69.85,78.74 A1.U2
  Bottom 0.254: A2.U2 57.15,80.01 60.96,80.01 62.23,81.28 64.77,81.28 66.04,80.01 69.22,80.01 A1.U2
N$54
  Top 0.254: A1A2SIDE2.32 86.36,90.81 87.63,89.53 87.63,87 74.3,73.66 68.58,73.66 66.67,75.56 A1.V2
  Bottom 0.254: A2.V2 53.98,75.56 57.78,75.56 59.05,74.3 64.77,74.3 66.04,75.56 A1.V2
N$55
  Top 0.254: A1A2SIDE1.10 95.89,119.38 94.61,120.65 93.34,120.65 87.63,126.36 87.63,127.64 87,128.27 85.72,128.27 85.09,128.91 85.09,130.18 84.45,130.81 76.2,130.81 A1.A1
  Bottom 0.254: A2.A1 63.5,129.54 67.31,129.54 68.58,128.27 71.12,128.27 72.39,129.54 75.56,129.54 A1.A1
N$56
  Top 0.254: 73.03,130.18 74.93,132.08 85.72,132.08 92.08,125.73 94.61,125.73 95.89,124.46 A1A2SIDE1.6 | 73.03,130.18 73.03,127.64 A1.B1 | 73.03,130.18 64.77,121.92 62.23,121.92 60.33,123.83 60.33,126.36 A2.B1
N$57
  Top 0.254: A1A2SIDE1.8 96.52,121.28 97.79,120.02 97.79,118.75 97.16,118.11 92.08,118.11 87,123.19 78.11,123.19 76.2,121.28 73.03,121.28 A1.D1 72.39,120.02 69.22,120.02 67.94,118.75 65.41,118.75 64.14,120.02 60.33,120.02 A2.D1
N$58
  Top 0.254: A1A2SIDE1.12 97.16,116.84 98.42,118.11 98.42,129.54 94.61,133.35 63.5,133.35 58.42,128.27 58.42,119.38 59.69,118.11 62.87,118.11 A2.E1
  Bottom 0.254: A1.E1 75.56,116.84 71.75,116.84 70.48,115.57 67.94,115.57 66.67,116.84 63.5,116.84 A2.E1
N$59
  Top 0.254: A2.F1 60.33,114.94 64.14,114.94 65.41,116.2 67.94,116.2 69.22,114.94 72.39,114.94 A1.F1
  Bottom 0.254: A1A2SIDE1.14 96.52,114.94 97.79,116.2 97.79,130.18 97.16,130.81 92.08,130.81 87,125.73 83.19,125.73 77.47,120.02 77.47,116.2 76.2,114.94 73.03,114.94 A1.F1
N$60
  Bottom 0.254: 78.11,110.49 76.2,110.49 A1.H1 | 78.11,110.49 94.61,110.49 95.89,111.76 A1A2SIDE1.16 | 78.11,110.49 73.66,106.05 71.75,106.05 67.31,110.49 63.5,110.49 A2.H1
N$61
  Top 0.254: 58.42,103.5 58.42,106.05 59.69,107.31 A2.J1 | 58.42,103.5 58.42,100.33 68.58,90.17 70.48,90.17 71.12,90.81 73.66,90.81 74.3,90.17 76.83,90.17 77.47,90.81 77.47,92.08 83.19,97.79 87,97.79 87.63,98.42 87.63,99.69 93.34,105.41 94.61,105.41 95.89,106.68 A1A2SIDE1.20 | 58.42,103.5 64.77,109.86 67.31,109.86 68.58,108.58 72.39,108.58 A1.J1
N$62
  Bottom 0.254: A1A2SIDE1.18 95.89,109.22 94.61,107.95 78.74,107.95 76.2,105.41 A1.K1 75.56,104.14 72.39,104.14 71.12,102.87 68.58,102.87 67.31,104.14 63.5,104.14 A2.K1
N$63
  Top 0.254: A2.L1 60.33,102.23 64.14,102.23 65.41,103.5 67.94,103.5 69.22,102.23 72.39,102.23 A1.L1
  Bottom 0.254: A1A2SIDE1.24 96.52,100.97 97.79,99.69 97.79,88.27 96.52,87 92.71,87 88.9,90.81 88.9,103.5 87,105.41 79.38,105.41 76.2,102.23 73.03,102.23 A1.L1
N$64
  Top 0.254: A1A2SIDE1.28 96.52,97.16 97.79,98.42 97.79,107.31 97.16,107.95 93.34,107.95 92.08,106.68 92.08,105.41 87,100.33 81.92,100.33 75.56,93.98 74.3,93.98 73.66,93.34 71.12,93.34 66.67,97.79 63.5,97.79 A2.M1
  Bottom 0.254: A1.M1 75.56,97.79 71.12,97.79 69.85,96.52 67.94,96.52 66.67,97.79 63.5,97.79 A2.M1
N$65  (via drill 0.61)
  Top 0.254: v92.71,102.87 94.61,102.87 95.89,104.14 A1A2SIDE1.22 | v84.45,81.92 v92.71,90.17 | v74.93,76.2 74.93,75.56 73.66,74.3 69.85,74.3 v69.22,74.93 | v57.15,74.3 57.15,76.2 55.24,78.11 v55.24,90.81
  Bottom 0.254: v92.71,90.17 v92.71,102.87 | v84.45,81.92 81.28,81.92 75.56,76.2 v74.93,76.2 | v69.22,74.93 67.94,74.93 66.67,73.66 57.78,73.66 v57.15,74.3 | v55.24,90.81 55.24,93.34 56.52,94.61 59.69,94.61 A2.N1 60.33,94.61 64.14,94.61 65.41,93.34 67.31,93.34 68.58,94.61 72.39,94.61 A1.N1
N$66  (via drill 0.61)
  Top 0.254: v95.25,85.72 97.79,88.27 97.79,92.08 96.52,93.34 A1A2SIDE1.30 | v81.92,84.45 v81.92,88.27 | v90.81,106.68 90.81,110.49 93.34,113.03 97.16,113.03 99.06,114.94 99.06,130.18 95.25,133.99 57.78,133.99 55.24,131.44 55.24,97.16 59.69,92.71 62.87,92.71 A2.P1
  Bottom 0.254: v95.25,85.72 93.98,84.45 v81.92,84.45 | v81.92,88.27 79.38,88.27 76.2,91.44 A1.P1 | v90.81,106.68 90.81,90.17 93.34,87.63 94.61,87.63 95.25,88.27 95.25,92.08 96.52,93.34 A1A2SIDE1.30
N$67
  Top 0.254: 58.42,78.11 58.42,87 59.69,88.27 A2.R1 | 58.42,78.11 58.42,74.3 61.59,71.12 65.41,71.12 66.67,71.12 67.94,72.39 72.39,72.39 73.03,72.39 73.66,71.75 78.74,71.75 83.19,71.75 98.42,87 98.42,93.98 97.16,95.25 95.89,95.25 95.25,95.89 95.25,97.16 96.52,98.42 A1A2SIDE1.26 | 58.42,78.11 68.58,88.27 72.39,88.27 A1.R1
N$68  (via drill 0.61)
  Top 0.254: v82.55,90.17 84.45,90.17 85.09,90.81 85.09,92.08 85.72,92.71 94.61,92.71 95.89,91.44 A1A2SIDE1.32 | v79.38,90.81 79.38,90.17 75.56,86.36 A1.S1 75.56,85.09 74.93,84.45 v71.75,84.45
  Bottom 0.254: v82.55,90.17 80.01,90.17 v79.38,90.81 | v71.75,84.45 71.12,83.82 68.58,83.82 67.31,85.09 63.5,85.09 A2.S1
N$69  (via drill 0.61)
  Top 0.254: v92.71,85.72 95.89,88.9 A1A2SIDE1.34
  Bottom 0.254: v92.71,85.72 80.01,85.72 77.47,83.19 76.2,83.19 | 76.2,83.19 73.03,83.19 A1.T1 | 76.2,83.19 70.48,77.47 68.58,77.47 67.94,78.11 65.41,78.11 64.77,77.47 62.23,77.47 61.59,78.11 59.05,78.11 58.42,77.47 55.88,77.47 55.24,78.11 55.24,80.64 56.52,81.92 59.69,81.92 A2.T1
N$70  (via drill 0.61)
  Top 0.254: v69.85,76.2 67.31,78.74 63.5,78.74 A2.U1
  Bottom 0.254: 92.08,83.19 79.38,83.19 76.2,80.01 A1.U1 | 92.08,83.19 94.61,83.19 98.42,87 98.42,111.76 97.16,113.03 95.89,113.03 95.25,113.67 95.25,125.09 96.52,126.36 A1A2SIDE1.4 | 92.08,83.19 80.64,71.75 74.93,71.75 73.03,73.66 72.39,73.66 v69.85,76.2
N$71  (via drill 0.61)
  Top 0.254: v93.34,132.08 95.89,129.54 A1A2SIDE1.2 | 62.87,73.03 60.33,75.56 A2.V1 | 62.87,73.03 v63.5,72.39 | 62.87,73.03 v75.56,73.03
  Bottom 0.254: v93.34,132.08 97.16,132.08 99.06,130.18 99.06,86.36 83.82,71.12 74.3,71.12 72.39,73.03 64.14,73.03 v63.5,72.39 | v75.56,73.03 73.03,75.56 A1.V1
N$72
  Top 0.254: A1A2SIDE1.17 93.98,109.86 93.98,111.12 A1A2SIDE1.15 | A2.C1 63.5,124.46 63.5,127 69.22,132.72 90.17,132.72 93.34,129.54 A1A2SIDE1.1
  Bottom 0.254: A1A2SIDE1.33 93.98,89.53 93.98,90.81 A1A2SIDE1.31 93.98,92.08 93.98,93.34 A1A2SIDE1.29 93.98,94.61 93.98,95.89 A1A2SIDE1.27 93.98,97.16 93.98,98.42 A1A2SIDE1.25 93.98,99.69 93.98,100.97 A1A2SIDE1.23 93.98,102.23 93.98,103.5 A1A2SIDE1.21 93.98,104.78 93.98,106.05 A1A2SIDE1.19 94.61,106.68 95.89,107.95 97.16,107.95 97.79,108.58 97.79,109.86 97.16,110.49 95.89,110.49 94.61,109.22 A1A2SIDE1.17 | A2.C1 63.5,123.19 67.31,123.19 68.58,121.92 71.12,121.92 72.39,123.19 75.56,123.19 A1.C1 | A1A2SIDE1.15 93.98,112.39 93.98,113.67 A1A2SIDE1.13 93.98,114.94 93.98,116.2 A1A2SIDE1.11 93.98,117.47 93.98,118.75 A1A2SIDE1.9 93.98,120.02 93.98,121.28 A1A2SIDE1.7 93.98,122.56 93.98,123.83 A1A2SIDE1.5 93.98,125.09 93.98,126.36 A1A2SIDE1.3 93.98,127.64 93.98,128.91 A1A2SIDE1.1
N$145
  Top 0.254: A3.C2 41.91,124.46 45.09,124.46 46.35,125.73 46.35,128.27 41.91,132.72 8.89,132.72 5.71,129.54 A3A4SIDE2.1
  Bottom 0.254: A4.C2 29.21,124.46 33.02,124.46 34.29,125.73 36.83,125.73 38.1,124.46 41.27,124.46 A3.C2 | A3A4SIDE2.33 5.08,89.53 5.08,90.81 A3A4SIDE2.31 5.08,92.08 5.08,93.34 A3A4SIDE2.29 5.08,94.61 5.08,95.89 A3A4SIDE2.27 5.08,97.16 5.08,98.42 A3A4SIDE2.25 5.08,99.69 5.08,100.97 A3A4SIDE2.23 5.08,102.23 5.08,103.5 A3A4SIDE2.21 5.08,104.78 5.08,106.05 A3A4SIDE2.19 5.08,107.31 5.08,108.58 A3A4SIDE2.17 5.08,109.86 5.08,111.12 A3A4SIDE2.15 5.08,112.39 5.08,113.67 A3A4SIDE2.13 5.08,114.94 5.08,116.2 A3A4SIDE2.11 5.08,117.47 5.08,118.75 A3A4SIDE2.9 5.08,120.02 5.08,121.28 A3A4SIDE2.7 5.08,122.56 5.08,123.83 A3A4SIDE2.5 5.08,125.09 5.08,126.36 A3A4SIDE2.3 5.08,127.64 5.08,128.91 A3A4SIDE2.1
N$146
  Bottom 0.254: 27.3,132.08 13.34,132.08 10.79,129.54 8.26,129.54 A3A4SIDE2.2 | 27.3,132.08 28.57,130.81 A4.A2 | 27.3,132.08 36.2,132.08 37.47,130.81 41.27,130.81 A3.A2
N$147
  Bottom 0.254: A3A4SIDE2.4 8.26,127 9.53,127 13.97,131.44 21.59,131.44 25.4,127.64 A4.B2 26.04,127.64 29.21,127.64 30.48,128.91 33.02,128.91 34.29,127.64 38.1,127.64 A3.B2
N$148
  Bottom 0.254: A3A4SIDE2.6 8.26,124.46 14.61,130.81 18.41,130.81 25.4,123.83 25.4,121.28 A4.D2 26.04,121.28 29.21,121.28 30.48,122.56 33.02,122.56 34.29,121.28 38.1,121.28 A3.D2
N$149
  Bottom 0.254: A3A4SIDE2.8 8.26,121.92 10.79,121.92 14.61,118.11 28.57,118.11 A4.E2 29.21,118.11 32.38,118.11 33.66,119.38 36.2,119.38 37.47,118.11 41.27,118.11 A3.E2
N$150
  Top 0.254: A3A4SIDE2.10 8.26,119.38 14.61,113.03 24.77,113.03 25.4,113.67 A4.F2
  Bottom 0.254: A3.F2 38.1,114.94 34.29,114.94 33.02,116.2 30.48,116.2 29.21,114.94 26.04,114.94 A4.F2
N$151
  Top 0.254: A3A4SIDE2.12 8.26,116.84 14.61,110.49 28.57,110.49 A4.H2
  Bottom 0.254: A3.H2 41.27,111.76 37.47,111.76 36.2,113.03 33.66,113.03 32.38,111.76 29.21,111.76 A4.H2
N$152
  Top 0.254: A3A4SIDE2.14 7.62,113.67 13.34,107.95 25.4,107.95 A4.J2
  Bottom 0.254: A3.J2 38.1,108.58 34.29,108.58 33.02,109.86 30.48,109.86 29.21,108.58 26.04,108.58 A4.J2
N$153
  Top 0.254: A3A4SIDE2.16 8.26,111.76 14.61,105.41 28.57,105.41 A4.K2
  Bottom 0.254: A3.K2 41.27,105.41 37.47,105.41 36.2,106.68 33.66,106.68 32.38,105.41 29.21,105.41 A4.K2
N$154
  Top 0.254: A3A4SIDE2.18 7.62,108.58 13.97,102.23 13.97,100.97 14.61,100.33 24.77,100.33 25.4,100.97 A4.L2
  Bottom 0.254: A3.L2 38.1,102.23 34.29,102.23 33.02,103.5 30.48,103.5 29.21,102.23 26.04,102.23 A4.L2
N$155
  Bottom 0.254: A3A4SIDE2.20 8.26,106.68 13.34,106.68 14.61,105.41 19.05,105.41 25.4,99.06 28.57,99.06 A4.M2 29.21,99.06 32.38,99.06 33.66,100.33 36.2,100.33 37.47,99.06 41.27,99.06 A3.M2
N$156
  Top 0.254: A3A4SIDE2.22 7.62,103.5 13.97,97.16 13.97,95.89 14.61,95.25 25.4,95.25 A4.N2
  Bottom 0.254: A3.N2 38.1,95.89 34.29,95.89 33.02,97.16 30.48,97.16 29.21,95.89 26.04,95.89 A4.N2
N$157
  Bottom 0.254: A3A4SIDE2.24 7.62,100.97 13.97,94.61 13.97,88.27 14.61,87.63 21.59,87.63 25.4,91.44 28.57,91.44 A4.P2 29.21,92.71 32.38,92.71 33.66,93.98 36.2,93.98 37.47,92.71 41.27,92.71 A3.P2
N$158
  Bottom 0.254: A3A4SIDE2.26 7.62,98.42 13.34,92.71 13.34,87.63 13.97,87 24.13,87 25.4,88.27 A4.R2 26.04,89.53 29.21,89.53 30.48,90.81 33.02,90.81 34.29,89.53 38.1,89.53 A3.R2
N$159
  Bottom 0.254: A3A4SIDE2.28 7.62,95.89 12.06,91.44 12.06,87.63 13.97,85.72 28.57,85.72 A4.S2 29.21,86.36 32.38,86.36 33.66,87.63 36.2,87.63 37.47,86.36 41.27,86.36 A3.S2
N$160
  Bottom 0.254: A3A4SIDE2.30 7.62,93.34 11.43,89.53 11.43,87 15.24,83.19 25.4,83.19 A4.T2 26.04,83.19 29.21,83.19 30.48,84.45 33.02,84.45 34.29,83.19 38.1,83.19 A3.T2
N$161
  Bottom 0.254: A3A4SIDE2.34 8.26,88.9 17.14,80.01 28.57,80.01 A4.U2 29.21,78.74 32.38,78.74 33.66,77.47 36.2,77.47 37.47,78.74 41.27,78.74 A3.U2
N$162
  Bottom 0.254: A3A4SIDE2.32 7.62,90.81 6.35,89.53 6.35,88.27 17.78,76.83 25.4,76.83 A4.V2 26.04,75.56 27.3,74.3 33.02,74.3 34.29,75.56 38.1,75.56 A3.V2
N$163
  Top 0.254: A3A4SIDE1.10 18.41,119.38 21.59,119.38 31.75,129.54 34.92,129.54 A4.A1
  Bottom 0.254: A3.A1 47.62,129.54 43.81,129.54 42.55,128.27 40.01,128.27 38.73,129.54 35.56,129.54 A4.A1
N$164
  Top 0.254: 38.73,130.18 41.27,127.64 44.45,127.64 A3.B1 | 38.73,130.18 36.83,132.08 27.94,132.08 20.32,124.46 18.41,124.46 A3A4SIDE1.6 | 38.73,130.18 36.2,127.64 32.38,127.64 A4.B1
N$165
  Top 0.254: A3.D1 44.45,120.02 40.64,120.02 39.37,118.75 36.83,118.75 35.56,120.02 32.38,120.02 A4.D1
  Bottom 0.254: A3A4SIDE1.8 18.41,121.92 21.59,121.92 24.77,118.75 27.3,118.75 28.57,120.02 31.75,120.02 A4.D1
N$166
  Top 0.254: A3A4SIDE1.12 18.41,116.84 26.67,116.84 27.94,115.57 30.48,115.57 31.75,116.84 34.92,116.84 A4.E1
  Bottom 0.254: A3.E1 47.62,116.84 43.81,116.84 42.55,115.57 40.01,115.57 38.73,116.84 35.56,116.84 A4.E1
N$167
  Top 0.254: A3.F1 44.45,113.67 40.64,113.67 39.37,112.39 36.83,112.39 35.56,113.67 32.38,113.67 A4.F1
  Bottom 0.254: A3A4SIDE1.14 18.41,114.3 22.86,114.3 24.77,112.39 27.3,112.39 28.57,113.67 31.75,113.67 A4.F1
N$168
  Top 0.254: A3A4SIDE1.16 18.41,111.76 26.67,111.76 27.94,113.03 30.48,113.03 31.75,111.76 34.92,111.76 A4.H1
  Bottom 0.254: A3.H1 47.62,110.49 43.81,110.49 42.55,109.22 40.01,109.22 38.73,110.49 35.56,110.49 A4.H1
N$169
  Top 0.254: A3.J1 44.45,107.31 40.64,107.31 39.37,106.05 36.83,106.05 35.56,107.31 32.38,107.31 A4.J1
  Bottom 0.254: A3A4SIDE1.20 18.41,106.68 24.13,106.68 24.77,106.05 27.3,106.05 28.57,107.31 31.75,107.31 A4.J1
N$170
  Top 0.254: A3A4SIDE1.18 18.41,109.22 24.13,109.22 24.77,109.86 27.3,109.86 31.75,105.41 34.92,105.41 A4.K1
  Bottom 0.254: A3.K1 47.62,104.14 43.81,104.14 42.55,102.87 40.01,102.87 38.73,104.14 35.56,104.14 A4.K1
N$171
  Top 0.254: A3A4SIDE1.24 18.41,101.6 22.86,101.6 24.77,103.5 27.3,103.5 28.57,102.23 31.75,102.23 A4.L1 32.38,102.23 35.56,102.23 36.83,103.5 39.37,103.5 40.64,102.23 44.45,102.23 A3.L1
N$172
  Top 0.254: A3A4SIDE1.28 18.41,96.52 24.13,96.52 24.77,97.16 27.3,97.16 27.94,96.52 30.48,96.52 31.75,97.79 34.92,97.79 A4.M1
  Bottom 0.254: A3.M1 47.62,97.79 43.81,97.79 42.55,96.52 40.01,96.52 38.73,97.79 35.56,97.79 A4.M1
N$173
  Top 0.254: A3.N1 44.45,95.89 40.64,95.89 39.37,97.16 36.83,97.16 35.56,95.89 32.38,95.89 A4.N1
  Bottom 0.254: A3A4SIDE1.22 17.78,103.5 24.13,97.16 24.13,93.98 24.77,93.34 27.3,93.34 28.57,94.61 31.75,94.61 A4.N1
N$174
  Top 0.254: A3A4SIDE1.30 18.41,93.98 24.13,93.98 27.94,90.17 30.48,90.17 31.75,91.44 34.92,91.44 A4.P1
  Bottom 0.254: A3.P1 47.62,91.44 43.81,91.44 42.55,90.17 40.01,90.17 38.73,91.44 35.56,91.44 A4.P1
N$175  (via drill 0.61)
  Top 0.254: v24.13,92.08 24.13,87.63 24.77,87 27.3,87 28.57,88.27 31.75,88.27 A4.R1 | A3.R1 45.09,89.53 45.09,92.71 46.35,93.98 46.35,96.52 42.55,100.33 40.01,100.33 39.37,99.69 36.83,99.69 36.2,100.33 33.66,100.33 33.02,99.69 30.48,99.69 29.84,100.33 27.3,100.33 26.04,99.06 18.41,99.06 A3A4SIDE1.26
  Bottom 0.254: v24.13,92.08 17.78,98.42 A3A4SIDE1.26
N$176
  Top 0.254: A3A4SIDE1.32 17.78,90.81 24.13,84.45 27.3,84.45 27.94,83.82 30.48,83.82 31.75,85.09 34.92,85.09 A4.S1
  Bottom 0.254: A3.S1 47.62,85.09 43.81,85.09 42.55,83.82 40.01,83.82 38.73,85.09 35.56,85.09 A4.S1
N$177
  Top 0.254: A3A4SIDE1.34 17.78,88.27 24.13,81.92 24.13,81.28 24.77,80.64 27.3,80.64 28.57,81.92 31.75,81.92 A4.T1
  Bottom 0.254: A3.T1 44.45,81.92 40.64,81.92 39.37,80.64 36.83,80.64 35.56,81.92 32.38,81.92 A4.T1
N$178  (via drill 0.61)
  Top 0.254: v2.54,125.73 15.88,125.73 17.14,127 A3A4SIDE1.4 | A4.U1 35.56,78.74 39.37,78.74 40.64,77.47 43.18,77.47 44.45,78.74 47.62,78.74 A3.U1
  Bottom 0.254: v2.54,125.73 2.54,88.27 17.78,73.03 44.45,73.03 47.62,76.2 47.62,78.74 A3.U1
N$179
  Top 0.254: A4.V1 32.38,75.56 36.2,75.56 37.47,74.3 43.18,74.3 44.45,75.56 A3.V1
  Bottom 0.254: A3A4SIDE1.2 17.78,128.91 16.51,127.64 16.51,121.28 15.88,120.65 13.34,120.65 10.79,123.19 6.99,123.19 6.35,123.83 6.35,130.18 5.71,130.81 4.45,130.81 3.81,130.18 3.81,88.27 18.41,73.66 42.55,73.66 44.45,75.56 A3.V1
N$180
  Top 0.254: 15.24,118.11 15.24,117.47 A3A4SIDE1.11 | 15.24,118.11 15.24,118.75 A3A4SIDE1.9 15.24,120.02 15.24,121.28 A3A4SIDE1.7 | 15.24,118.11 26.04,118.11 31.11,123.19 34.92,123.19 A4.C1
  Bottom 0.254: A3A4SIDE1.33 15.24,89.53 15.24,90.81 A3A4SIDE1.31 15.24,92.08 15.24,93.34 A3A4SIDE1.29 15.24,94.61 15.24,95.89 A3A4SIDE1.27 15.24,97.16 15.24,98.42 A3A4SIDE1.25 15.24,99.69 15.24,100.97 A3A4SIDE1.23 15.24,102.23 15.24,103.5 A3A4SIDE1.21 14.61,104.14 9.53,104.14 8.26,105.41 6.99,105.41 6.35,106.05 6.35,107.31 6.99,107.95 15.24,107.95 | A4.C1 35.56,123.19 39.37,123.19 40.64,121.92 43.18,121.92 44.45,123.19 47.62,123.19 A3.C1 | A3A4SIDE1.7 15.24,122.56 15.24,123.83 A3A4SIDE1.5 15.24,125.09 15.24,126.36 A3A4SIDE1.3 15.24,127.64 15.24,128.91 A3A4SIDE1.1 | 15.24,107.95 15.24,108.58 A3A4SIDE1.17 15.24,109.86 15.24,111.12 A3A4SIDE1.15 15.24,112.39 15.24,113.67 A3A4SIDE1.13 15.24,114.94 15.24,116.2 A3A4SIDE1.11 | 15.24,107.95 15.24,107.31 A3A4SIDE1.19
N$253
  Top 0.254: B3B4SIDE2.5 5.71,55.88 6.99,54.61 28.57,54.61 B4.C2 29.21,54.61 32.38,54.61 33.66,55.88 36.2,55.88 37.47,54.61 41.27,54.61 B3.C2
  Bottom 0.254: B3B4SIDE2.33 5.08,20.95 5.08,22.23 B3B4SIDE2.31 5.08,23.5 5.08,24.77 B3B4SIDE2.29 5.08,26.04 5.08,27.3 B3B4SIDE2.27 5.08,28.57 5.08,29.84 B3B4SIDE2.25 5.08,31.11 5.08,32.38 B3B4SIDE2.23 5.08,33.66 5.08,34.92 B3B4SIDE2.21 5.08,36.2 5.08,37.47 B3B4SIDE2.19 5.08,38.73 5.08,40.01 B3B4SIDE2.17 5.08,41.27 5.08,42.55 B3B4SIDE2.15 5.08,43.81 5.08,45.09 B3B4SIDE2.13 5.08,46.35 5.08,47.62 B3B4SIDE2.11 5.08,48.9 5.08,50.16 B3B4SIDE2.9 5.08,51.44 5.08,52.7 B3B4SIDE2.7 5.08,53.98 5.08,55.24 B3B4SIDE2.5 5.08,56.52 5.08,57.78 B3B4SIDE2.3 5.08,59.05 5.08,60.33 B3B4SIDE2.1
N$254
  Top 0.254: B3B4SIDE2.2 8.26,60.96 13.34,60.96 14.61,59.69 28.57,59.69 B4.A2
  Bottom 0.254: B3.A2 41.27,60.96 37.47,60.96 36.2,62.23 30.48,62.23 29.21,60.96 B4.A2
N$255
  Top 0.254: B3B4SIDE2.4 8.26,58.42 13.34,58.42 14.61,57.15 25.4,57.15 B4.B2
  Bottom 0.254: B3.B2 38.1,57.78 34.29,57.78 33.02,59.05 30.48,59.05 29.21,57.78 26.04,57.78 B4.B2
N$256
  Bottom 0.254: B3B4SIDE2.6 7.62,55.24 13.97,48.9 13.97,47.62 14.61,46.99 22.23,46.99 25.4,50.16 B4.D2 26.04,51.44 29.21,51.44 30.48,52.7 33.02,52.7 34.29,51.44 38.1,51.44 B3.D2
N$257
  Top 0.254: B3B4SIDE2.8 8.26,53.34 14.61,46.99 28.57,46.99 B4.E2
  Bottom 0.254: B3.E2 41.27,48.26 37.47,48.26 36.2,49.53 33.66,49.53 32.38,48.26 29.21,48.26 B4.E2
N$258
  Top 0.254: B3B4SIDE2.10 8.26,50.8 14.61,44.45 25.4,44.45 B4.F2 26.04,43.81 29.21,43.81 30.48,42.55 33.02,42.55 34.29,43.81 38.1,43.81 B3.F2
N$259
  Top 0.254: B3B4SIDE2.12 8.26,48.26 14.61,41.91 28.57,41.91 B4.H2
  Bottom 0.254: B3.H2 41.91,41.91 45.09,41.91 46.35,43.18 46.35,45.72 45.72,46.35 43.18,46.35 42.55,45.72 40.01,45.72 39.37,46.35 36.83,46.35 36.2,45.72 33.66,45.72 33.02,46.35 30.48,46.35 29.84,45.72 27.3,45.72 26.67,46.35 20.32,46.35 18.41,44.45 17.14,44.45 16.51,43.81 16.51,42.55 17.14,41.91 28.57,41.91 B4.H2
N$260
  Top 0.254: B3B4SIDE2.14 8.26,45.72 14.61,39.37 24.77,39.37 25.4,38.73 B4.J2 26.04,37.47 29.21,37.47 30.48,36.2 33.02,36.2 34.29,37.47 38.1,37.47 B3.J2
N$261
  Top 0.254: 25.4,35.56 24.13,36.83 14.61,36.83 8.26,43.18 B3B4SIDE2.16 | 25.4,35.56 28.57,35.56 B4.K2 | 25.4,35.56 31.11,29.84 33.02,29.84 33.66,30.48 36.2,30.48 36.83,29.84 39.37,29.84 40.01,30.48 42.55,30.48 43.18,29.84 45.72,29.84 46.35,30.48 46.35,33.02 45.09,34.29 41.91,34.29 B3.K2
N$262
  Bottom 0.254: B3B4SIDE2.18 7.62,40.01 13.97,33.66 13.97,19.68 14.61,19.05 15.88,19.05 16.51,19.68 16.51,31.11 17.14,31.75 25.4,31.75 B4.L2 26.04,32.38 29.21,32.38 30.48,33.66 33.02,33.66 34.29,32.38 38.1,32.38 B3.L2
N$263
  Bottom 0.254: 20.32,20.95 24.13,24.77 24.13,26.67 25.4,27.94 28.57,27.94 B4.M2 | 20.32,20.95 17.78,18.41 13.97,18.41 13.34,19.05 13.34,31.75 7.62,37.47 B3B4SIDE2.20 | 20.32,20.95 24.13,17.14 26.67,17.14 27.3,17.78 29.84,17.78 30.48,17.14 33.02,17.14 33.66,17.78 36.2,17.78 36.83,17.14 39.37,17.14 43.18,20.95 43.18,23.5 41.91,24.77 41.91,27.94 B3.M2
N$264
  Top 0.254: B3B4SIDE2.22 8.26,35.56 14.61,29.21 22.23,29.21 25.4,26.04 B4.N2
  Bottom 0.254: B3.N2 38.1,26.04 34.29,26.04 33.02,27.3 30.48,27.3 29.21,26.04 26.04,26.04 B4.N2
N$265
  Top 0.254: B3B4SIDE2.24 8.26,33.02 14.61,26.67 21.59,26.67 25.4,22.86 28.57,22.86 B4.P2
  Bottom 0.254: B3.P2 41.27,22.86 37.47,22.86 36.2,24.13 33.66,24.13 32.38,22.86 29.21,22.86 B4.P2
N$266
  Top 0.254: B3B4SIDE2.26 8.26,30.48 14.61,24.13 20.95,24.13 25.4,19.68 B4.R2
  Bottom 0.254: B3.R2 38.1,19.68 34.29,19.68 33.02,20.95 30.48,20.95 29.21,19.68 26.04,19.68 B4.R2
N$267
  Top 0.254: B3.S2 41.27,16.51 37.47,16.51 36.2,17.78 33.66,17.78 32.38,16.51 29.21,16.51 B4.S2
  Bottom 0.254: B3B4SIDE2.28 7.62,27.3 12.7,22.23 12.7,18.41 14.61,16.51 28.57,16.51 B4.S2
N$268
  Bottom 0.254: B3B4SIDE2.30 7.62,24.77 12.06,20.32 12.06,17.78 16.51,13.34 25.4,13.34 B4.T2 26.04,13.34 29.21,13.34 30.48,14.61 33.02,14.61 34.29,13.34 38.1,13.34 B3.T2
N$269
  Bottom 0.254: B3B4SIDE2.34 8.26,20.32 18.41,10.16 28.57,10.16 B4.U2 29.21,10.16 32.38,10.16 33.66,11.43 36.2,11.43 37.47,10.16 41.27,10.16 B3.U2
N$270
  Bottom 0.254: B3B4SIDE2.32 7.62,22.23 6.35,20.95 6.35,19.68 19.05,6.99 25.4,6.99 B4.V2 26.04,5.71 27.3,4.45 33.02,4.45 34.29,5.71 38.1,5.71 B3.V2
N$271  (via drill 0.61)
  Top 0.254: v25.4,62.23 26.04,62.87 43.18,62.87 45.09,60.96 47.62,60.96 B3.A1
  Bottom 0.254: 26.67,60.96 28.57,62.87 41.91,62.87 43.18,61.59 43.18,59.05 42.55,58.42 40.01,58.42 38.73,59.69 35.56,59.69 B4.A1 | 26.67,60.96 24.13,58.42 24.13,57.78 17.78,51.44 B3B4SIDE1.10 | 26.67,60.96 v25.4,62.23
N$272
  Top 0.254: B3B4SIDE1.6 18.41,55.88 24.13,55.88 24.77,55.24 27.3,55.24 28.57,56.52 31.75,56.52 B4.B1 32.38,57.78 35.56,57.78 36.83,59.05 39.37,59.05 40.64,57.78 44.45,57.78 B3.B1
N$273
  Top 0.254: B3B4SIDE1.8 18.41,53.34 26.67,53.34 28.57,51.44 31.75,51.44 B4.D1 32.38,50.16 35.56,50.16 36.83,48.9 39.37,48.9 40.64,50.16 44.45,50.16 B3.D1
N$274
  Top 0.254: B4.E1 35.56,46.99 39.37,46.99 40.64,45.72 43.18,45.72 44.45,46.99 47.62,46.99 B3.E1
  Bottom 0.254: B3B4SIDE1.12 18.41,48.26 20.32,48.26 27.94,55.88 30.48,55.88 31.11,55.24 33.66,55.24 34.29,55.88 36.83,55.88 44.45,48.26 47.62,48.26 B3.E1
N$275
  Top 0.254: B3B4SIDE1.14 18.41,45.72 24.13,45.72 24.77,46.35 27.3,46.35 28.57,45.09 31.75,45.09 B4.F1
  Bottom 0.254: B3.F1 44.45,43.81 40.64,43.81 39.37,42.55 36.83,42.55 35.56,43.81 32.38,43.81 B4.F1
N$276
  Top 0.254: B3.H1 47.62,41.91 43.81,41.91 42.55,43.18 40.01,43.18 38.73,41.91 35.56,41.91 B4.H1
  Bottom 0.254: B3B4SIDE1.16 18.41,43.18 24.13,43.18 24.77,42.55 27.3,42.55 27.94,43.18 30.48,43.18 31.75,41.91 34.92,41.91 B4.H1
N$277
  Bottom 0.254: B3B4SIDE1.20 18.41,38.1 22.86,38.1 24.77,40.01 27.3,40.01 28.57,38.73 31.75,38.73 B4.J1 32.38,38.73 35.56,38.73 36.83,40.01 39.37,40.01 40.64,38.73 44.45,38.73 B3.J1
N$278
  Top 0.254: 41.91,38.1 44.45,35.56 47.62,35.56 B3.K1 | 41.91,38.1 40.01,40.01 37.47,40.01 36.83,39.37 34.29,39.37 33.66,40.01 31.11,40.01 30.48,39.37 27.94,39.37 26.67,40.64 18.41,40.64 B3B4SIDE1.18 | 41.91,38.1 39.37,35.56 35.56,35.56 B4.K1
N$279
  Top 0.254: B4.L1 32.38,32.38 36.2,32.38 37.47,33.66 40.01,33.66 41.27,32.38 44.45,32.38 B3.L1
  Bottom 0.254: B3B4SIDE1.24 18.41,33.02 24.13,33.02 27.94,36.83 30.48,36.83 31.11,36.2 33.66,36.2 34.29,36.83 36.83,36.83 41.27,32.38 44.45,32.38 B3.L1
N$280
  Bottom 0.254: B3B4SIDE1.28 18.41,27.94 24.13,27.94 26.04,29.84 27.3,29.84 27.94,30.48 30.48,30.48 31.75,29.21 34.92,29.21 B4.M1 35.56,29.21 38.73,29.21 40.01,30.48 42.55,30.48 43.81,29.21 47.62,29.21 B3.M1
N$281
  Top 0.254: B3B4SIDE1.22 18.41,35.56 27.94,26.04 31.75,26.04 B4.N1 32.38,26.04 35.56,26.04 36.83,27.3 39.37,27.3 40.64,26.04 44.45,26.04 B3.N1
N$282
  Top 0.254: B3B4SIDE1.30 18.41,25.4 21.59,25.4 26.04,20.95 27.3,20.95 27.94,20.32 30.48,20.32 31.75,21.59 34.92,21.59 B4.P1 35.56,22.86 38.73,22.86 40.01,24.13 42.55,24.13 43.81,22.86 47.62,22.86 B3.P1
N$283
  Top 0.254: 46.35,14.61 46.35,17.14 45.09,18.41 B3.R1 | 46.35,14.61 46.35,5.08 45.09,3.81 22.23,3.81 6.35,19.68 6.35,36.2 6.99,36.83 8.26,36.83 13.34,31.75 15.88,31.75 17.14,30.48 B3B4SIDE1.26 | 46.35,14.61 40.01,20.95 37.47,20.95 36.2,19.68 32.38,19.68 B4.R1
N$284
  Top 0.254: B3B4SIDE1.32 18.41,22.86 27.3,13.97 30.48,13.97 31.75,15.24 34.92,15.24 B4.S1
  Bottom 0.254: B3.S1 47.62,15.24 43.81,15.24 42.55,13.97 40.01,13.97 38.73,15.24 35.56,15.24 B4.S1
N$285
  Top 0.254: 29.84,12.06 31.75,12.06 B4.T1 | 29.84,12.06 28.57,12.06 27.3,10.79 24.77,10.79 17.78,17.78 17.78,19.68 B3B4SIDE1.34 | 29.84,12.06 34.29,7.62 36.2,7.62 40.64,12.06 44.45,12.06 B3.T1
N$286
  Bottom 0.254: 41.91,6.35 44.45,8.89 47.62,8.89 B3.U1 | 41.91,6.35 39.37,3.81 19.68,3.81 3.81,19.68 3.81,61.59 4.45,62.23 15.88,62.23 16.51,61.59 16.51,60.33 17.78,59.05 B3B4SIDE1.4 | 41.91,6.35 39.37,8.89 35.56,8.89 B4.U1
N$287
  Top 0.254: B4.V1 32.38,5.71 36.2,5.71 37.47,4.45 43.18,4.45 44.45,5.71 B3.V1
  Bottom 0.254: B3B4SIDE1.2 17.78,61.59 16.51,62.87 3.81,62.87 3.17,62.23 3.17,19.05 19.68,2.54 41.27,2.54 44.45,5.71 B3.V1
N$288
  Top 0.254: B4.C1 35.56,53.34 39.37,53.34 40.64,52.07 43.18,52.07 44.45,53.34 47.62,53.34 B3.C1
  Bottom 0.254: B3B4SIDE1.11 15.24,48.9 15.24,50.16 B3B4SIDE1.9 15.24,51.44 15.24,52.7 B3B4SIDE1.7 15.24,53.98 15.24,55.24 B3B4SIDE1.5 15.24,56.52 15.24,57.15 | 15.24,57.15 15.24,57.78 B3B4SIDE1.3 | B3B4SIDE1.1 15.24,60.33 15.24,59.05 B3B4SIDE1.3 | B3B4SIDE1.33 15.24,20.95 15.24,22.23 B3B4SIDE1.31 15.24,23.5 15.24,24.77 B3B4SIDE1.29 15.24,26.04 15.24,27.3 B3B4SIDE1.27 15.24,28.57 15.24,29.84 B3B4SIDE1.25 15.24,31.11 15.24,32.38 B3B4SIDE1.23 15.24,33.66 15.24,34.92 B3B4SIDE1.21 15.24,36.2 15.24,37.47 B3B4SIDE1.19 15.24,38.73 15.24,40.01 B3B4SIDE1.17 15.24,41.27 15.24,42.55 B3B4SIDE1.15 15.24,43.81 15.24,44.45 | 15.24,44.45 15.24,45.09 B3B4SIDE1.13 | 15.24,44.45 6.99,44.45 6.35,45.09 6.35,56.52 6.99,57.15 8.26,57.15 9.53,58.42 14.61,58.42 B3B4SIDE1.3 | 15.24,57.15 18.41,57.15 24.77,63.5 42.55,63.5 43.81,62.23 43.81,61.59 47.62,57.78 47.62,54.61 B3.C1

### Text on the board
tPlace: A4 | A3 | A2 | A1 | 1 | 1 | 1 | 1 | 34 | 34 | 34 | 34 | A4 | A3 | A2 | A1 | B4 | B3 | B2 | B1 | 1 | 1 | 1 | 1 | 34 | 34 | 34 | 34 | B4 | B3 | B2 | B1
bPlace: 2 | 1 | 2 | 1 | 2 | 1 | 2 | 1 | A | A | A | A | B | B | B | B | C | C | C | C | D | D | D | D | E | E | E | E | F | F | F | F | H | H | H | H | J | J | J | J | K | K | K | K | L | L | L | L | M | M | M | M | N | N | N | N | P | P | P | P | R | R | R | R | S | S | S | S | T | T | T | T | U | U | U | U | V | V | V | V | 2 | 1 | 2 | 1 | 2 | 1 | 2 | 1 | 2 | 1 | 2 | 1 | 2 | 1 | 2 | 1 | A | A | A | A | B | B | B | B | C | C | C | C | D | D | D | D | E | E | E | E | F | F | F | F | H | H | H | H | J | J | J | J | K | K | K | K | L | L | L | L | M | M | M | M | N | N | N | N | P | P | P | P | R | R | R | R | S | S | S | S | T | T | T | T | U | U | U | U | V | V | V | V | 2 | 1 | 2 | 1 | 2 | 1 | 2 | 1
tNames: A3A4SIDE2 | A3A4SIDE1 | A1A2SIDE2 | A1A2SIDE1 | B3B4SIDE2 | B3B4SIDE1 | B1B2SIDE2 | B1B2SIDE1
